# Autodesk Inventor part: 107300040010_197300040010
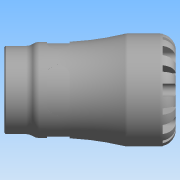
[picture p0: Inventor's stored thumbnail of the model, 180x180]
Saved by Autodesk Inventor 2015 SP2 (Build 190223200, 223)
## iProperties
Created: 2016-12
Part Number: 107300040010_197300040010
Material: Generic
Description: PLASSON FEMALE INTEGRAL BRASS THREAD 40X1" SERIES 1
Document SubType Name: Modeling
Designer: KIM
Density: 1 g/cm^3
Appearance: Default
Author: KIM
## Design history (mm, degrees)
derived "1073.ipt"
feature "Solid1::1073.ipt"
tag "TaggingFeature1"
body "Solid1"
other parameters: "d0" = 106, "d1" = 30.66, "d6" = 73, "d8" = 59.5, "d13" = 8, "d14" = 8, "d15" = 0, "d17" = 360 deg, "d19" = 8 deg, "d20" = 0.8, "d21" = 0.8, "d22" = 8 deg, "d24" = 0, "d26" = 360 deg, "d32" = 7, "d33" = 7, "d39" = 0.90873, "d42" = 30.291, "d43" = 54.6, "d46" = 3.33333, "d47" = 19, "d48" = 28.77645, "d50" = 4.62, "d51" = 0.7, "d54" = 14, "d55" = 8.8, "d57" = 15.68, "d58" = 0, "d68" = 360 deg, "d72" = 0.8, "d74" = 0, "d76" = 11.9, "H_" = 106, "l_" = 73, "G_" = 30.291, "l_2" = 19, "d9" = 10, "d49" = 14
